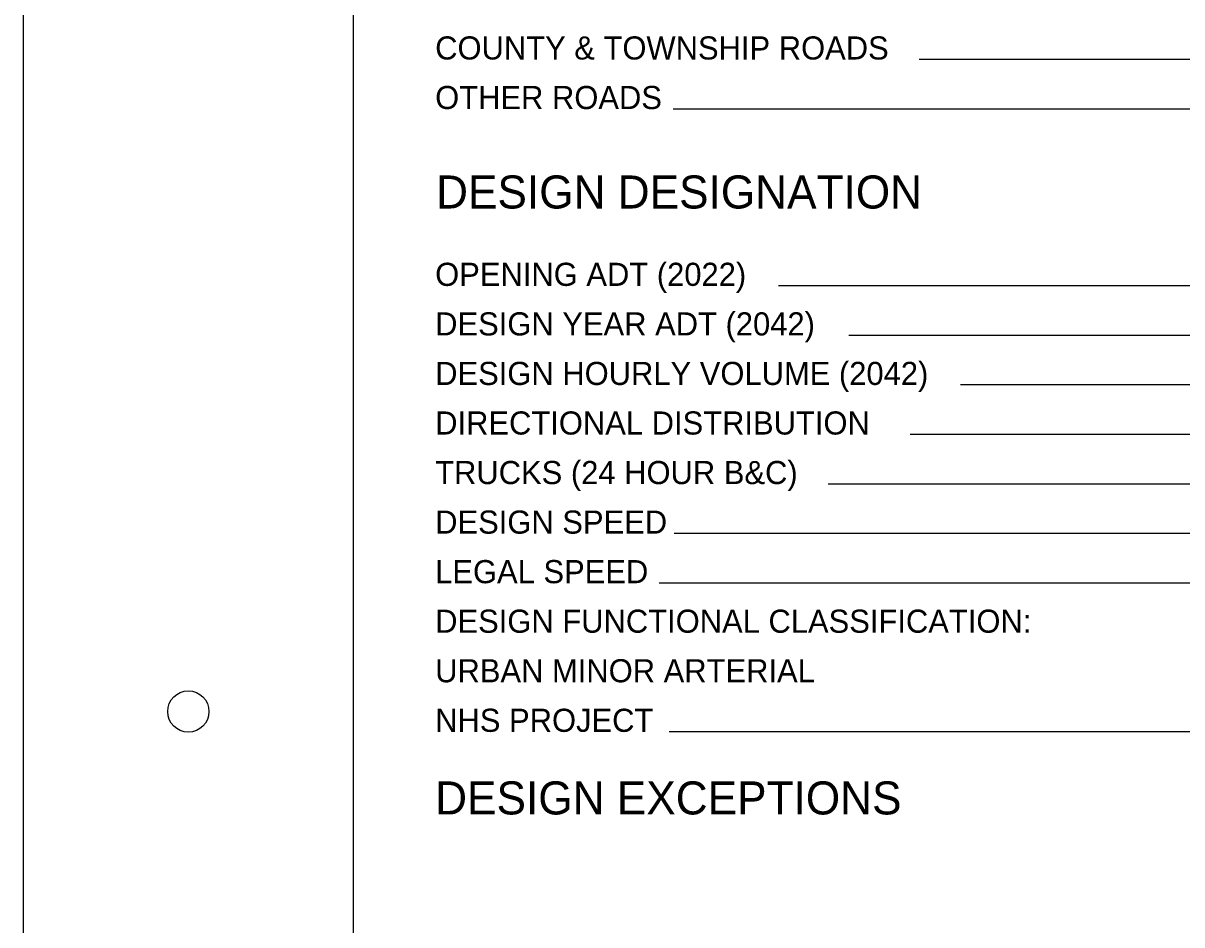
# Model space of a CAD drawing. Extents: x 421.3 to 469.3, y 221.6 to 248.2.
# Drawn here: x 421.31 to 428.32, y 227.09 to 232.55 of the extents above; entities that cross this region are included whole.
import ezdxf

# ---------------------------------------------------------------- set-up
doc = ezdxf.new("R2010")
doc.units = 0
for name, color, linetype in [('SH_Border', 7, 'Continuous'), ('SH_Cut_Line', 7, 'Continuous'), ('SH_Data', 7, 'Continuous')]:
    doc.layers.add(name, color=color, linetype=linetype)

msp = doc.modelspace()

# ---------------------------------------------------------------- linework, layer by layer
at = {"layer": 'SH_Border'}
msp.add_lwpolyline([(423.3078, 243.1284), (454.8078, 243.1284), (454.8078, 222.1284), (423.3078, 222.1284)], close=True, dxfattribs=at)
msp.add_circle((422.3078, 228.3784), 0.125, dxfattribs=at)
at = {"layer": 'SH_Cut_Line'}
msp.add_lwpolyline([(421.3078, 221.6284), (455.3078, 221.6284), (455.3078, 243.6284), (421.3078, 243.6284)], close=True, dxfattribs=at)
at = {"layer": 'SH_Data'}
for p, q in [((429.5078, 232.3259), (426.7317, 232.3259)), ((429.5078, 232.0259), (425.2426, 232.0259)), ((429.4502, 230.9554), (425.8814, 230.9554)), ((429.4446, 230.6554), (426.3065, 230.6554)), ((429.4446, 230.3554), (426.9836, 230.3554)), ((429.4446, 230.0554), (426.6789, 230.0554)), ((429.4446, 229.7554), (426.1824, 229.7554)), ((429.4446, 229.4554), (425.2494, 229.4554)), ((429.4446, 229.1554), (425.1592, 229.1554)), ((429.4446, 228.2554), (425.2193, 228.2554))]:
    msp.add_line(p, q, dxfattribs=at)

# ---------------------------------------------------------------- texts
for s, height, p in [('COUNTY & TOWNSHIP ROADS', 0.14, (423.8022, 232.3259)), ('OTHER ROADS', 0.14, (423.8022, 232.0259)), ('DESIGN DESIGNATION', 0.2, (423.8078, 231.4239)), ('OPENING ADT (2022)', 0.14, (423.8022, 230.9554)), ('DESIGN YEAR ADT (2042)', 0.14, (423.8022, 230.6554)), ('DESIGN HOURLY VOLUME (2042)', 0.14, (423.8022, 230.3554)), ('DIRECTIONAL DISTRIBUTION', 0.14, (423.8022, 230.0554)), ('TRUCKS (24 HOUR B&C)', 0.14, (423.8022, 229.7554)), ('DESIGN SPEED', 0.14, (423.8022, 229.4554)), ('LEGAL SPEED', 0.14, (423.8022, 229.1554)), ('DESIGN FUNCTIONAL CLASSIFICATION:', 0.14, (423.8022, 228.8554)), ('URBAN MINOR ARTERIAL                            ', 0.14, (423.8022, 228.5554)), ('NHS PROJECT', 0.14, (423.8022, 228.2554)), ('DESIGN EXCEPTIONS', 0.2, (423.8022, 227.7554))]:
    msp.add_text(s, height=height, dxfattribs=at).set_placement(p)

doc.saveas('drawing.dxf')
